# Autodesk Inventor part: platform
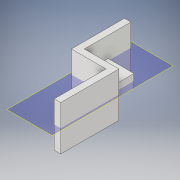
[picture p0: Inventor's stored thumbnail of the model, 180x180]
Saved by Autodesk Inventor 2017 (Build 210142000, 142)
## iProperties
Created: 2017-04
Part Number: platform
Material: LCP Plastic
Document SubType Name: Modeling
Designer: 1460374
Density: 1.626 g/cm^3
Appearance: Smooth - White
Author: 1460374
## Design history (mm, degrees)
sketch "Sketch1"
  geometry: L1 (-324.026, 5.525)-(-324.026, 11.875) reference; L2 (-332.942, 11.875)-(-324.026, 5.525) reference; L3 (-332.942, 11.875)-(-315.942, 11.875); L4 (-315.942, 11.875)-(-315.942, -9.969); L5 (-315.942, -9.969)-(-332.942, -9.969); L6 (-332.942, -9.969)-(-332.942, 11.875); 1 further point
  constraints: 8 end point, 2 parallel, 1 horizontal, 1 perpendicular
  dimensions: "d0" = 17 distance of L4.end L5.end; "d1" = 21.844 distance of L3.end L4.end
extrude "Extrusion1" new body sketch "Sketch1" distance "d2" = 3.175; taper "d3" = 0 deg
sketch "Sketch2"
  geometry: L1 (332.942, 11.875)-(332.942, -9.969) reference; L2 (315.942, 11.875)-(332.942, 11.875) reference; L3 (332.942, -9.969)-(329.767, -9.969); L4 (329.767, -9.969)-(329.767, 11.875); L5 (329.767, 11.875)-(332.942, 11.875); L6 (332.942, 11.875)-(332.942, -9.969); 1 further point
  constraints: 8 end point, 2 parallel, 1 horizontal, 1 perpendicular, 1 point on line
  dimensions: "d4" = 3.175 distance of L4.end L5.end
extrude "Extrusion2" join sketch "Sketch2" distance "d5" = 22.86; taper "d6" = 0 deg
sketch "Sketch3"
  geometry: L1 (0, 0)-(-28.575, 0); L2 (-28.575, 0)-(-28.575, 21.844); L3 (-28.575, 21.844)-(0, 21.844); L4 (0, 21.844)-(0, 0); 1 further point
  constraints: 8 end point, 2 parallel, 1 horizontal, 1 perpendicular
  dimensions: "d7" = 28.575 distance of L2.end L3.end
extrude "Extrusion3" join sketch "Sketch3" distance "d8" = 3.175; taper "d9" = 0 deg
workplane "Work Plane1"
workplane "Work Plane2"
sketch "Sketch5"
  geometry: L1 (20.175, 22.86)-(3.175, 22.86) reference; L2 (3.175, 22.86)-(3.175, 0) reference; L3 (5.325, 22.86)-(5.325, 13.335); L4 (5.325, 13.335)-(18.025, 13.335); L5 (18.025, 13.335)-(18.025, 22.86); L6 (3.175, 22.86)-(20.175, 22.86) reference; L7 (18.025, 32.385)-(5.325, 13.335); L8 (5.325, 32.385)-(18.025, 13.335); 2 further points
  constraints: 10 end point, 3 midpoint, 2 point on line, 1 parallel
  dimensions: "d14" = 12.7 distance of L4.end L3.end
extrude "Extrusion5" join sketch "Sketch5" stored distance "d15" = 6.35; taper "d16" = 0 deg
workplane "Work Plane6"
sketch "Sketch6"
  geometry: L1 (5.325, 22.86)-(18.025, 13.335); C1 r 1.905 at (11.675, 18.098); 1 further point
  constraints: 2 end point, 1 centre point, 1 midpoint
  dimensions: "d24" = 3.81 diameter of C1
extrude "Extrusion6" join sketch "Sketch6" stored distance "d17" = 6.35; taper "d18" = 0 deg
sketch "Sketch13"
  geometry: C1 r 1.905 at (11.675, 18.098) reference; C2 r 4.001 at (11.675, 18.098); 1 further point
  constraints: 1 centre point, 1 coincident
  dimensions: "d28" = 8.001 diameter of C2
extrude "Extrusion9" join sketch "Sketch13" distance "d29" = 1.9558; taper "d30" = 0 deg
body "Solid1"
node "Reference1"
node "Reference2"
node "Reference3"
node "Reference4"
node "Reference5"
node "Reference6"
